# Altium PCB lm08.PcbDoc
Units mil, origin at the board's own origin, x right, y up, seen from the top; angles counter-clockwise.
Board outline 1110 x 1610 mil, 2 copper layers (Top, Bottom), stack 12.7 mil thick; 1 components, 0 nets, 34 pads, 0 vias.
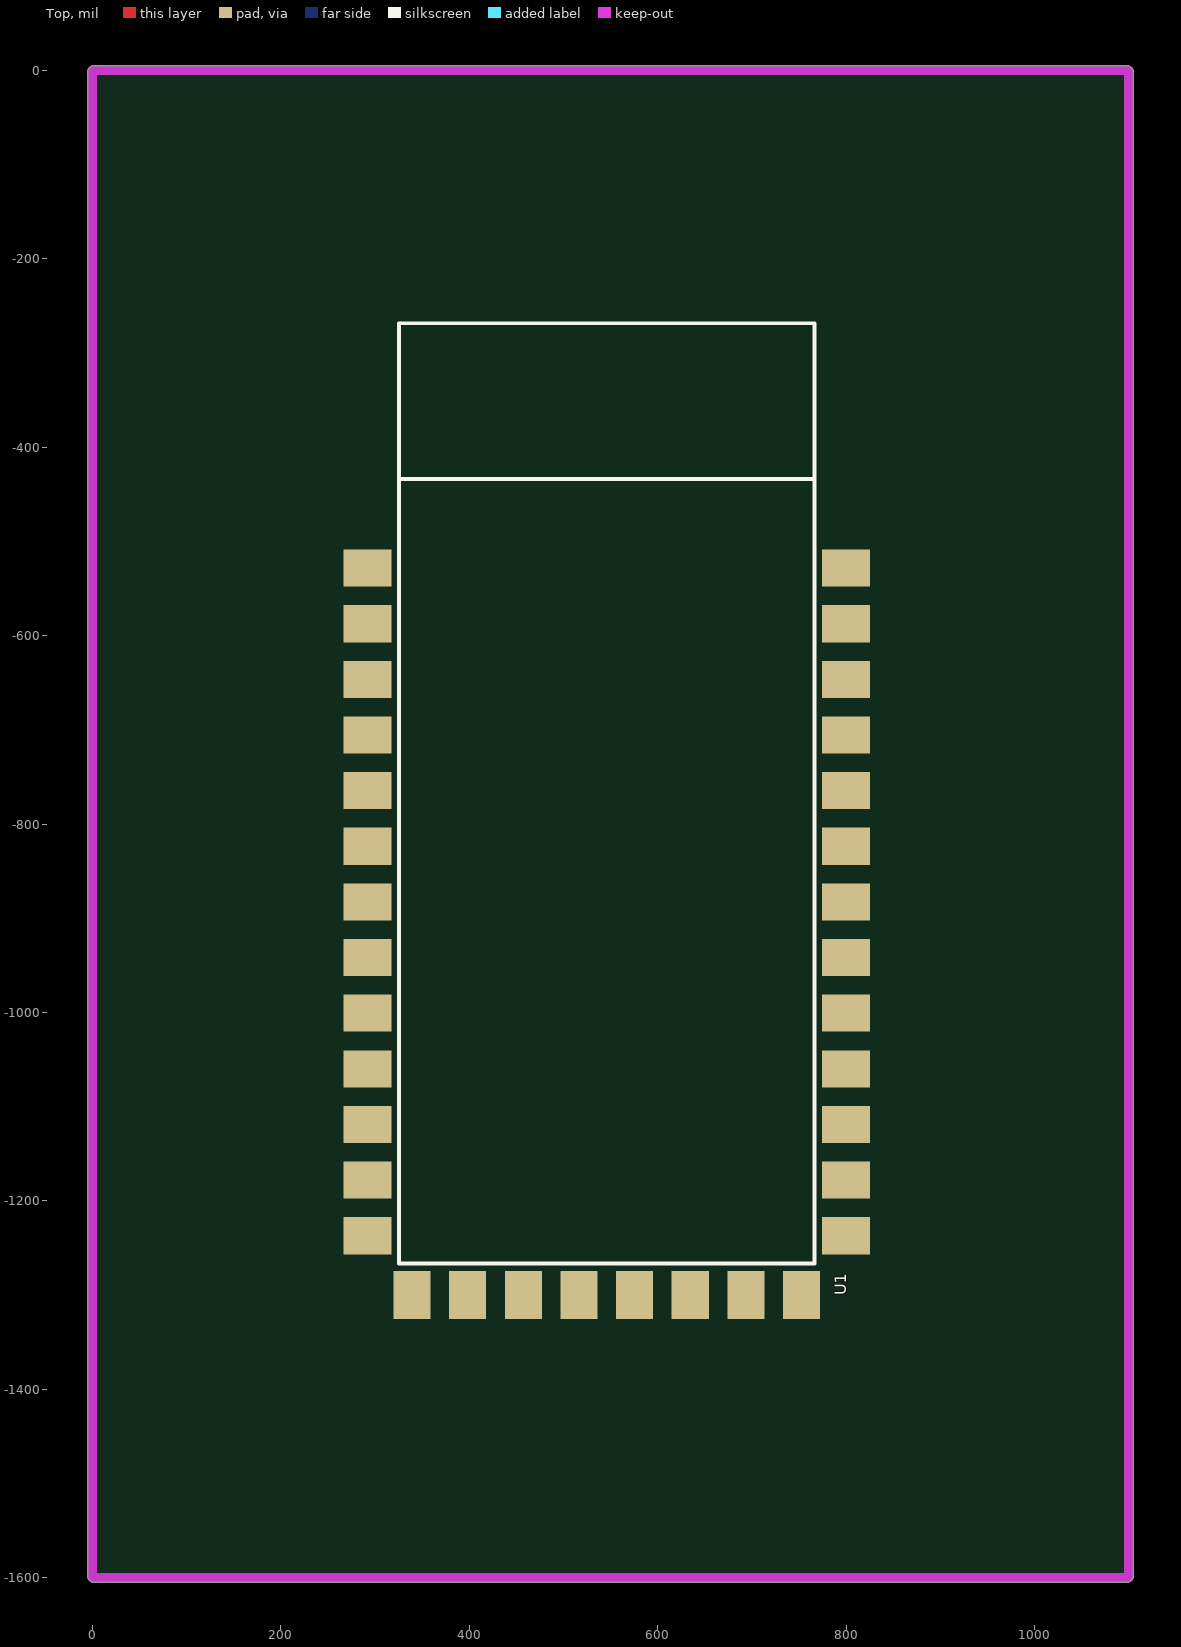
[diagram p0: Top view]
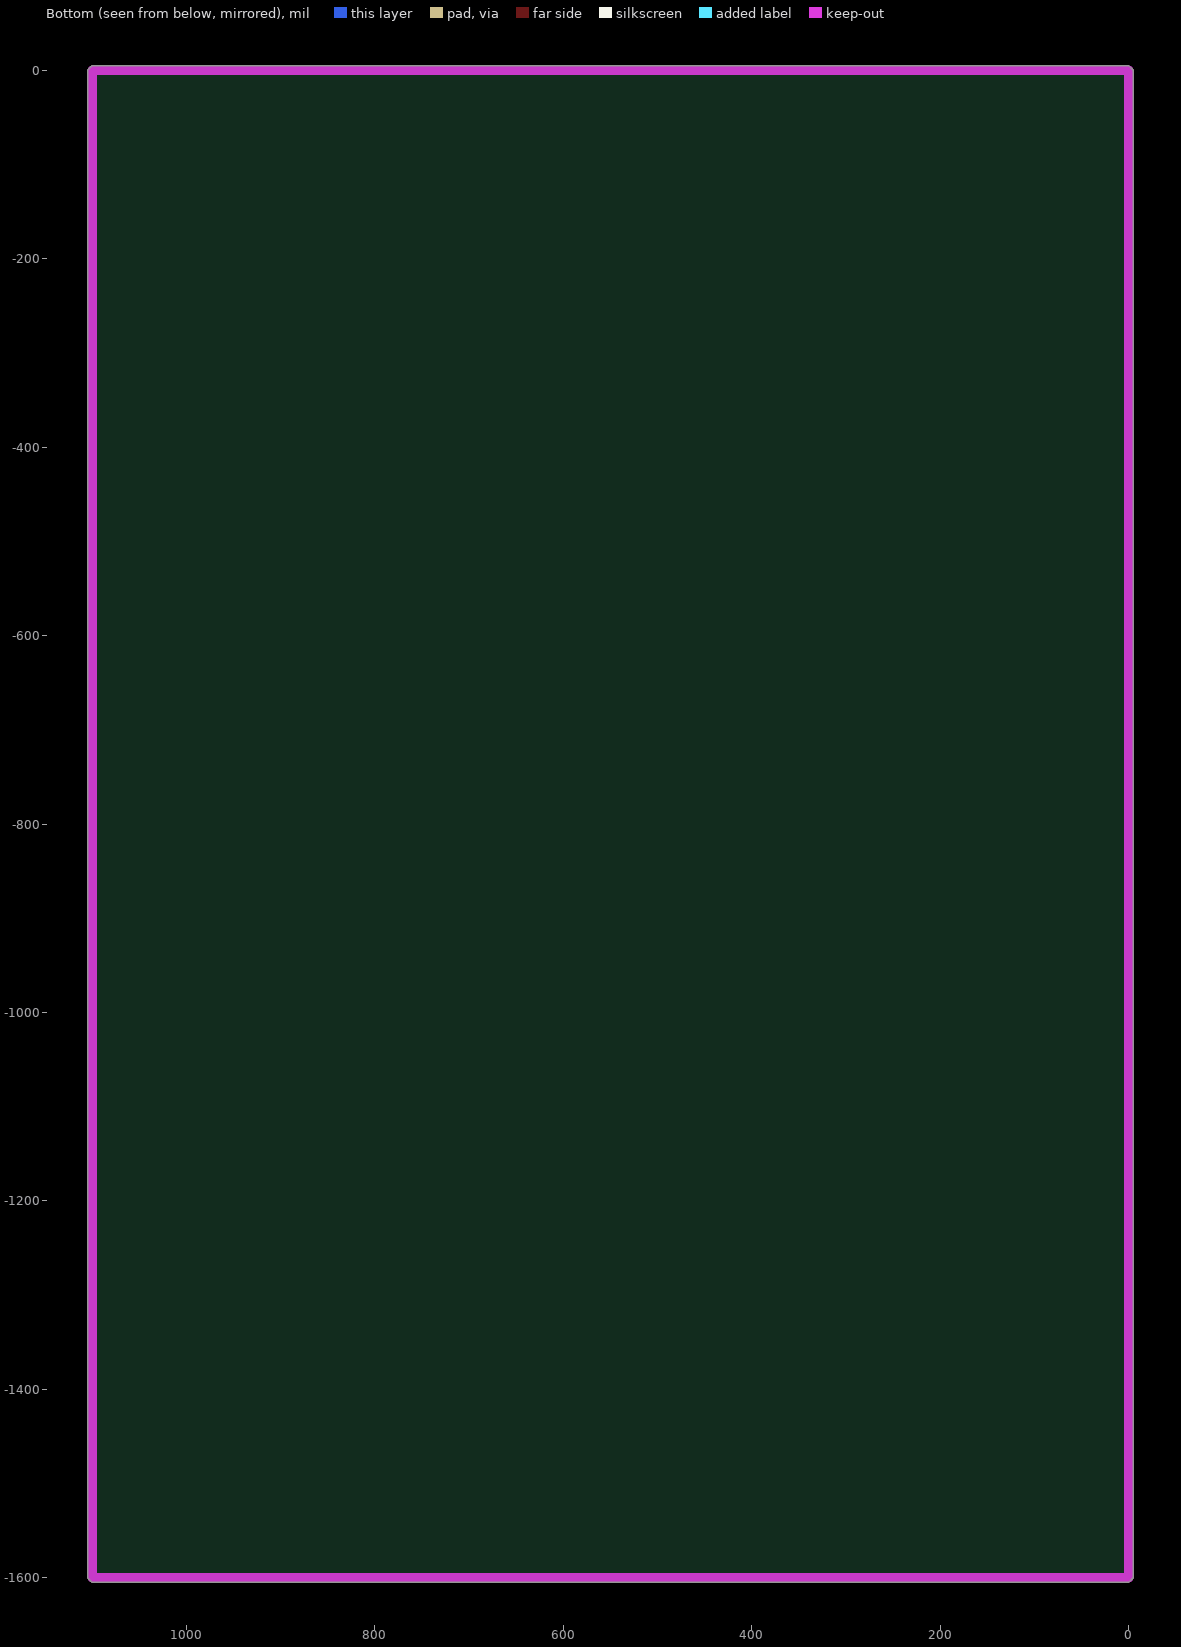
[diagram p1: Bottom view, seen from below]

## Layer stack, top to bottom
Top: signal copper 1.35
Dielectric: dielectric 10, FR-4, Dk 4.3
Bottom: signal copper 1.35

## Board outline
-5,-1600 0,-1605 1100,-1605 1105,-1600 1105,0 1100,5 0,5 -5,0

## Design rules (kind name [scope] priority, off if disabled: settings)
Clearance "'Default' PADS rule_18" [All] p1: gap=6
Clearance "'Default' PADS rule_15" [IsVia vs IsVia] p2: gap=6
ComponentClearance "'Default' PADS rule_12" [All] p1: gap=6 collisioncheckmode=3 verticalgap=10 showdistances=FALSE
FlightTimeFalling "'Default' PADS rule_10" [All] p1: maximum=10.00
FlightTimeRising "'Default' PADS rule_9" [All] p1: maximum=10.00
Length "'Default' PADS rule_5" [All] p1: maxlimit=50000 minlimit=0
MatchedLengths "'Default' PADS rule_11" [InNetClass('All Nets')] p1: tolerance=200 checknetsindiffpair=TRUE checkdiffpairvsdiffpair=TRUE checkothers=TRUE
MaxMinImpedance "'Default' PADS rule_8" [All] p1: minimum=50.00 maximum=150.0
ParallelSegment "'Default' PADS rule_7" [All] p1: limit=1000 gap=200
ParallelSegment "'Default' PADS rule_6" [All] p2: limit=1000 gap=200
PlaneClearance "'Default' PADS rule_14" [All] p1: clearance=6
PlaneConnect "Power Plane Connect Style - from global settings" [All] p1: planeconnectstyle=Relief reliefexpansion=20 reliefentries=2 reliefconductorwidth=15 reliefairgap=10
PolygonConnect [All] p1: connectstyle=Relief reliefconductorwidth=10 reliefentries=4 polygonreliefangle="90 Angle"
RoutingLayers "'Default' PADS rule_3" [All] p1: top layer_v5=TRUE bottom layer_v5=TRUE
RoutingPriority "'Default' PADS rule_2" [All] p1: routingpriority=3
RoutingTopology "'Default' PADS rule" [All] p1: topology=Shortest
RoutingVias "'Default' PADS rule_4" [All] p1: holewidth=37 width=55 viastyle="Through Hole" minholewidth=37 minwidth=55 maxholewidth=37 maxwidth=55
SMDToCorner "'Default' PADS rule_16" [All] p1: distance=60000
SMDToPlane "'Default' PADS rule_17" [All] p1: distance=60000
SilkscreenOverComponentPads [All] p1: minsilkscreentomaskgap=10
SolderMaskExpansion [All] p1: expansion=4
Width "'Default' PADS rule_13" [All] p1: maxlimit=12 minlimit=12 preferedwidth=12
21 further rules are at their usual default settings.

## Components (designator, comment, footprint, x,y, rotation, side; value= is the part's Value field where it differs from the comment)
U1 "LM08" LM08 800,-1300 r90 top

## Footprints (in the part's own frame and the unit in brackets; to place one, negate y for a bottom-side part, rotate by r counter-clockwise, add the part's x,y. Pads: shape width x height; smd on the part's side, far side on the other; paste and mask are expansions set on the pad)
LM08 [mm]
  rect 1x1.3 smd: 1(19.6,12.9) 2(18.1,12.9) 3(16.6,12.9) 4(15.1,12.9) 5(13.6,12.9) 6(12.1,12.9) 7(10.6,12.9) 8(9.1,12.9) 9(7.6,12.9) 10(6.1,12.9) 11(4.6,12.9) 12(3.1,12.9) 13(1.6,12.9) 22(1.6,0) 23(3.1,0) 24(4.6,0) 25(6.1,0) 26(7.6,0) 27(9.1,0) 28(10.6,0) 29(12.1,0) 30(13.6,0) 31(15.1,0) 32(16.6,0) 33(18.1,0) 34(19.6,0)
  rect 1.3x1 smd: 14(0,11.7) 15(0,10.2) 16(0,8.7) 17(0,7.2) 18(0,5.7) 19(0,4.2) 20(0,2.7) 21(0,1.2)
  silkscreen extent 0.85,0.85 26.2,12.05

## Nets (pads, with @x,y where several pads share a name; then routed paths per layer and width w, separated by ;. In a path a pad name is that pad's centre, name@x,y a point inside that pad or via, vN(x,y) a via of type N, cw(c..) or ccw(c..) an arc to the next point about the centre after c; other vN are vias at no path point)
pads on no net: U1.1 U1.2 U1.3 U1.4 U1.5 U1.6 U1.7 U1.8 U1.9 U1.10 U1.11 U1.12 U1.13 U1.14 U1.15 U1.16 U1.17 U1.18 U1.19 U1.20 U1.21 U1.22 U1.23 U1.24 U1.25 U1.26 U1.27 U1.28 U1.29 U1.30 U1.31 U1.32 U1.33 U1.34

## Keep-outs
Keep-Out Layer:
  lines w10: 0,-1600 1100,-1600 1100,0 0,0 0,-1600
